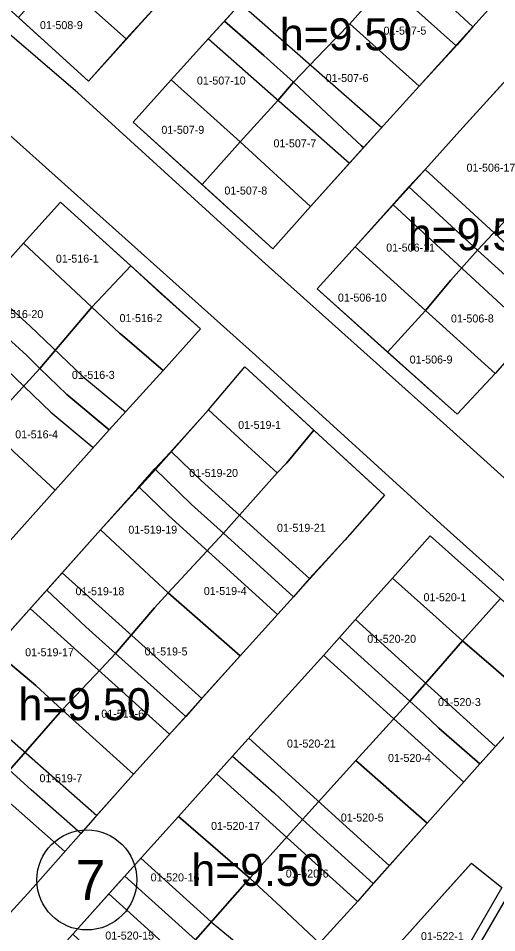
# Model space of a CAD drawing. Extents: x 413946 to 415528, y 4453939 to 4454944.
# Drawn here: x 415344.5 to 415404.3, y 4454500.5 to 4454614.8 of the extents above; entities that cross this region are included whole.
import ezdxf

# ---------------------------------------------------------------- set-up
doc = ezdxf.new("R2010")
doc.units = 0
for name, color, linetype in [('0_KADASTRO', 7, 'Continuous'), ('Level 27', 7, 'Continuous'), ('Level 28', 7, 'Continuous'), ('Level 30', 7, 'Continuous'), ('Level 58', 7, 'Continuous'), ('Level 59', 7, 'Continuous'), ('Level 62', 7, 'Continuous')]:
    doc.layers.add(name, color=color, linetype=linetype)

msp = doc.modelspace()

# ---------------------------------------------------------------- linework, layer by layer
at = {"layer": '0_KADASTRO'}
for points in [[(415392.52, 4454621.45), (415394.32, 4454623.55), (415398.92, 4454628.85), (415405.91, 4454636.32), (415407.9, 4454634.44), (415409.39, 4454633.1), (415414.54, 4454628.38), (415401.36, 4454613.72), (415394.73, 4454619.9)], [(415370.29, 4454614.44), (415372.34, 4454616.67), (415377.12, 4454622.06), (415381.68, 4454627.2), (415383.59, 4454629.35), (415387.91, 4454625.49), (415392.52, 4454621.45), (415390.64, 4454619.39), (415385.96, 4454614.09), (415382.84, 4454610.86), (415378.94, 4454606.78), (415375.2, 4454610.12)], [(415349.19, 4454620.07), (415354.05, 4454625.45), (415355.88, 4454627.42), (415364.64, 4454619.57), (415362.7, 4454617.4), (415358.02, 4454612.21), (415352.81, 4454616.85)], [(415385.96, 4454614.09), (415390.64, 4454619.39), (415392.52, 4454621.45), (415394.73, 4454619.9), (415401.36, 4454613.72), (415399.38, 4454611.47), (415394.62, 4454606.3)], [(415344.53, 4454614.87), (415349.19, 4454620.07), (415352.81, 4454616.85), (415358.02, 4454612.21), (415353.29, 4454606.93)], [(415363.64, 4454607.07), (415368.36, 4454612.28), (415370.29, 4454614.44), (415375.2, 4454610.12), (415378.94, 4454606.78), (415376.95, 4454604.5), (415372.27, 4454599.33)], [(415378.94, 4454606.78), (415382.84, 4454610.86), (415385.96, 4454614.09), (415394.62, 4454606.3), (415389.82, 4454600.98), (415387.66, 4454598.63), (415387.42, 4454598.86), (415384.43, 4454601.65)], [(415401.93, 4454585.81), (415408.86, 4454593.19), (415411.08, 4454595.65), (415415.48, 4454600.57), (415406.83, 4454608.55), (415404.81, 4454606.31), (415400.11, 4454601.13), (415395.44, 4454595.94), (415393.34, 4454593.71)], [(415358.88, 4454601.81), (415363.64, 4454607.07), (415372.27, 4454599.33), (415367.5, 4454594)], [(415372.27, 4454599.33), (415376.95, 4454604.5), (415378.94, 4454606.78), (415384.43, 4454601.65), (415387.42, 4454598.86), (415387.66, 4454598.63), (415381.06, 4454591.26)], [(415367.5, 4454594), (415372.27, 4454599.33), (415381.06, 4454591.26), (415376.36, 4454585.96)], [(415386.63, 4454586.21), (415393.26, 4454593.63), (415393.34, 4454593.71), (415401.93, 4454585.81), (415398.6, 4454582.05), (415395.42, 4454578.26)], [(415401.93, 4454585.81), (415408.86, 4454593.19), (415410.07, 4454592.09), (415417.49, 4454585.37), (415410.74, 4454577.85)], [(415345.19, 4454586.67), (415349.81, 4454591.81), (415358.59, 4454583.85), (415353.71, 4454578.68), (415352.4, 4454579.91)], [(415338.41, 4454579.14), (415345.19, 4454586.67), (415352.4, 4454579.91), (415353.71, 4454578.68), (415347.21, 4454571), (415345.81, 4454572.43), (415345.58, 4454572.64)], [(415381.87, 4454580.97), (415386.63, 4454586.21), (415395.42, 4454578.26), (415390.69, 4454573.05)], [(415395.42, 4454578.26), (415398.6, 4454582.05), (415401.93, 4454585.81), (415410.74, 4454577.85), (415404.14, 4454570.37)], [(415353.71, 4454578.68), (415358.59, 4454583.85), (415362.36, 4454580.4), (415367.29, 4454575.96), (415362.62, 4454570.74), (415357.53, 4454575.12), (415357.16, 4454575.43)], [(415331.71, 4454571.7), (415338.41, 4454579.14), (415345.58, 4454572.64), (415345.81, 4454572.43), (415347.21, 4454571), (415343.29, 4454566.72), (415340.55, 4454563.89), (415339.16, 4454564.98), (415336.73, 4454567.11)], [(415347.21, 4454571), (415353.71, 4454578.68), (415357.16, 4454575.43), (415357.53, 4454575.12), (415362.62, 4454570.74), (415355.89, 4454563.36), (415350.59, 4454567.77)], [(415390.69, 4454573.05), (415395.42, 4454578.26), (415404.14, 4454570.37), (415399.37, 4454565.32)], [(415340.55, 4454563.89), (415343.29, 4454566.72), (415347.21, 4454571), (415350.59, 4454567.77), (415355.89, 4454563.36), (415349.15, 4454555.82), (415343.97, 4454560.6)], [(415368.28, 4454565.86), (415372.83, 4454571.21), (415381.47, 4454563.29), (415378.1, 4454559.22), (415376.89, 4454557.98), (415373.23, 4454561.29)], [(415361.58, 4454558.45), (415363.47, 4454560.48), (415368.28, 4454565.86), (415373.23, 4454561.29), (415376.89, 4454557.98), (415370.19, 4454550.42), (415366.17, 4454554.02)], [(415333.75, 4454556.43), (415335.17, 4454557.74), (415340.55, 4454563.89), (415343.97, 4454560.6), (415349.15, 4454555.82), (415342.51, 4454548.4)], [(415370.19, 4454550.42), (415376.89, 4454557.98), (415378.1, 4454559.22), (415381.47, 4454563.29), (415385.25, 4454559.79), (415390.31, 4454555.19), (415385.34, 4454549.56), (415380.92, 4454544.76), (415378.94, 4454542.48)], [(415354.8, 4454550.86), (415359.45, 4454556.04), (415361.58, 4454558.45), (415366.17, 4454554.02), (415370.19, 4454550.42), (415363.25, 4454542.97), (415359.69, 4454546.31)], [(415348.08, 4454543.29), (415354.8, 4454550.86), (415359.69, 4454546.31), (415363.25, 4454542.97), (415361.56, 4454541.11), (415356.69, 4454535.4), (415352.98, 4454538.72)], [(415363.25, 4454542.97), (415370.19, 4454550.42), (415378.94, 4454542.48), (415372.27, 4454535.1)], [(415391.29, 4454544.81), (415396.02, 4454550.11), (415404.8, 4454542.24), (415400.07, 4454536.98), (415396.34, 4454540.31)], [(415384.69, 4454537.39), (415386.64, 4454539.58), (415391.29, 4454544.81), (415396.34, 4454540.31), (415400.07, 4454536.98), (415396.21, 4454532.57), (415394.99, 4454531.17), (415393.47, 4454529.44), (415392.23, 4454530.56)], [(415341.4, 4454535.86), (415341.92, 4454536.44), (415346.16, 4454541.18), (415348.08, 4454543.29), (415352.98, 4454538.72), (415356.69, 4454535.4), (415354.88, 4454533.47), (415350.02, 4454528.33), (415346.7, 4454531.38)], [(415356.69, 4454535.4), (415361.56, 4454541.11), (415363.25, 4454542.97), (415372.27, 4454535.1), (415367.54, 4454529.87), (415365.46, 4454527.51)], [(415400.07, 4454536.98), (415404.8, 4454542.24), (415413.64, 4454534.32), (415409.05, 4454529.17), (415403.93, 4454533.63)], [(415371.29, 4454522.55), (415376.51, 4454517.95), (415380.07, 4454514.64), (415386.73, 4454522), (415393.47, 4454529.44), (415392.23, 4454530.56), (415384.69, 4454537.39), (415382.7, 4454535.18), (415377.92, 4454529.87)], [(415393.47, 4454529.44), (415394.99, 4454531.17), (415396.21, 4454532.57), (415400.07, 4454536.98), (415403.93, 4454533.63), (415409.05, 4454529.17), (415402.21, 4454521.58), (415397.09, 4454526.04), (415395.21, 4454527.84)], [(415334.73, 4454528.41), (415336.75, 4454530.66), (415341.4, 4454535.86), (415346.7, 4454531.38), (415350.02, 4454528.33), (415343.44, 4454520.82), (415339.68, 4454524.05)], [(415350.02, 4454528.33), (415354.88, 4454533.47), (415356.69, 4454535.4), (415365.46, 4454527.51), (415363.68, 4454525.56), (415358.94, 4454520.32)], [(415386.73, 4454522), (415393.47, 4454529.44), (415395.21, 4454527.84), (415397.09, 4454526.04), (415402.21, 4454521.58), (415395.65, 4454514.16)], [(415343.44, 4454520.82), (415350.02, 4454528.33), (415358.94, 4454520.32), (415354.15, 4454514.93), (415352.33, 4454512.88), (415346.15, 4454518.33)], [(415364.56, 4454515.03), (415371.29, 4454522.55), (415376.51, 4454517.95), (415380.07, 4454514.64), (415378.18, 4454512.56), (415373.45, 4454507.29)], [(415380.07, 4454514.64), (415386.73, 4454522), (415395.65, 4454514.16), (415388.87, 4454506.65)], [(415341.28, 4454518.41), (415340.61, 4454517.67), (415338.82, 4454515.67), (415336.69, 4454513.32), (415334.67, 4454511.02), (415332.54, 4454508.6), (415332.05, 4454508.05), (415330.07, 4454505.8), (415333.85, 4454502.42), (415338.85, 4454497.94), (415340.8, 4454500.07), (415345.71, 4454505.4), (415352.33, 4454512.88), (415346.15, 4454518.33), (415343.44, 4454520.82), (415341.32, 4454518.46)], [(415357.83, 4454507.56), (415359.92, 4454509.88), (415364.56, 4454515.03), (415373.45, 4454507.29), (415366.69, 4454499.58)], [(415373.45, 4454507.29), (415378.18, 4454512.56), (415380.07, 4454514.64), (415388.87, 4454506.65), (415386.96, 4454504.42), (415382.17, 4454499.17), (415377.4, 4454503.69)], [(415392.33, 4454499.34), (415399.98, 4454507.85), (415401.18, 4454509.19), (415404.98, 4454506.12), (415398.11, 4454494.21), (415397.39, 4454495.06)], [(415351.32, 4454500.3), (415357.29, 4454506.95), (415357.83, 4454507.56), (415366.69, 4454499.58), (415359.95, 4454492.25), (415358.81, 4454493.29), (415356.52, 4454495.46)], [(415366.69, 4454499.58), (415373.45, 4454507.29), (415377.4, 4454503.69), (415382.17, 4454499.17), (415377.39, 4454493.8), (415375.5, 4454491.76), (415370.54, 4454496.39)]]:
    msp.add_lwpolyline(points, close=True, dxfattribs=at)
at = {"layer": 'Level 27'}
for p, q in [((415376.36, 4454585.96), (415358.88, 4454601.81)), ((415349.81, 4454591.81), (415367.29, 4454575.96)), ((415399.37, 4454565.32), (415381.87, 4454580.97)), ((415372.83, 4454571.21), (415390.31, 4454555.19))]:
    msp.add_line(p, q, dxfattribs=at)
for points in [[(415402.79, 4454662.09), (415384.8, 4454642.09), (415371.27, 4454626.96), (415362.7, 4454617.4), (415353.29, 4454606.93)], [(415358.88, 4454601.81), (415363.64, 4454607.07), (415368.36, 4454612.28), (415372.34, 4454616.67), (415381.68, 4454627.2), (415390.33, 4454636.85), (415397, 4454644.32), (415403.75, 4454651.87), (415408.42, 4454657.05)], [(415409.56, 4454622.84), (415401.36, 4454613.72), (415394.62, 4454606.3), (415389.82, 4454600.98), (415381.06, 4454591.26), (415376.36, 4454585.96)], [(415381.87, 4454580.97), (415386.63, 4454586.21), (415395.44, 4454595.94), (415400.11, 4454601.13), (415406.83, 4454608.55), (415409.43, 4454611.44)], [(415286.85, 4454521.84), (415291.59, 4454527.07), (415298.37, 4454534.61), (415305.09, 4454541.94), (415318.4, 4454556.81), (415325.06, 4454564.24), (415331.71, 4454571.7), (415338.41, 4454579.14), (415345.19, 4454586.67), (415349.81, 4454591.81)], [(415367.29, 4454575.96), (415362.62, 4454570.74), (415355.89, 4454563.36), (415349.15, 4454555.82), (415342.51, 4454548.4), (415329.15, 4454533.51), (415322.3, 4454525.96), (415315.86, 4454518.71), (415309.04, 4454511.18), (415304.47, 4454506.04)], [(415409.03, 4454575.92), (415404.14, 4454570.37), (415399.37, 4454565.32)], [(415310.02, 4454500.93), (415314.69, 4454506.15), (415321.35, 4454513.54), (415328.03, 4454520.98), (415332.79, 4454526.26), (415336.75, 4454530.66), (415346.16, 4454541.18), (415354.8, 4454550.86), (415361.66, 4454558.38), (415368.28, 4454565.86), (415372.83, 4454571.21)], [(415390.31, 4454555.19), (415385.34, 4454549.56), (415378.94, 4454542.48), (415372.27, 4454535.1), (415363.68, 4454525.56), (415358.94, 4454520.32), (415352.33, 4454512.88), (415345.71, 4454505.4), (415340.8, 4454500.07), (415336.86, 4454495.7), (415332.18, 4454490.43), (415327.52, 4454485.21)], [(415333.05, 4454480.09), (415337.73, 4454485.35), (415344.49, 4454492.72), (415351.32, 4454500.3), (415359.92, 4454509.88), (415364.56, 4454515.03), (415371.29, 4454522.55), (415377.92, 4454529.87), (415382.7, 4454535.18), (415386.64, 4454539.58), (415391.29, 4454544.81), (415396.02, 4454550.11)], [(415396.02, 4454550.11), (415404.8, 4454542.24), (415408.62, 4454538.82)], [(415408.5, 4454528.56), (415402.21, 4454521.58), (415395.65, 4454514.16), (415386.96, 4454504.42), (415382.17, 4454499.17), (415368.73, 4454484.21), (415360.01, 4454474.61), (415355.28, 4454469.41), (415350.53, 4454464.22)], [(415371.07, 4454475.69), (415374.23, 4454479.2), (415380.92, 4454486.66), (415392.34, 4454499.33), (415401.18, 4454509.19)], [(415401.18, 4454509.19), (415404.98, 4454506.12), (415398.11, 4454494.21), (415394.18, 4454488.09), (415389.06, 4454479.28), (415383.11, 4454471.06)]]:
    msp.add_lwpolyline(points, dxfattribs=at)
at = {"layer": 'Level 28'}
msp.add_line((415353.29, 4454606.93), (415335.77, 4454622.85), dxfattribs=at)
at = {"layer": 'Level 58'}
msp.add_circle((415353.09, 4454507.08), 6.25, dxfattribs=at)
at = {"layer": 'Level 59'}
for points in [[(415399.22, 4454611.36), (415381.6, 4454627.11)], [(415372.32, 4454616.65), (415389.96, 4454601.13)], [(415368.29, 4454612.2), (415385.94, 4454596.67)], [(415395.4, 4454595.89), (415412.67, 4454580)], [(415391.37, 4454591.45), (415408.68, 4454575.52)], [(415346.02, 4454576.29), (415340.42, 4454581.37)], [(415352.59, 4454570.01), (415346.02, 4454576.29)], [(415348.59, 4454565.53), (415341.86, 4454571.97)], [(415352.59, 4454570.01), (415357.92, 4454565.58)], [(415348.59, 4454565.53), (415353.89, 4454561.12)], [(415367.39, 4454557.02), (415363.64, 4454560.63)], [(415367.39, 4454557.02), (415380.95, 4454544.71)], [(415363.3, 4454552.62), (415359.63, 4454556.16)], [(415363.3, 4454552.62), (415376.93, 4454540.25)], [(415367.45, 4454529.75), (415349.99, 4454545.47)], [(415363.44, 4454525.29), (415345.99, 4454540.99)], [(415404.19, 4454523.78), (415386.68, 4454539.63)], [(415400.2, 4454519.3), (415382.68, 4454535.16)], [(415336.73, 4454530.64), (415354.32, 4454515.12)], [(415332.72, 4454526.18), (415350.34, 4454510.64)], [(415373.34, 4454524.81), (415390.91, 4454508.85)], [(415369.32, 4454520.35), (415386.92, 4454504.37)], [(415359.84, 4454509.79), (415368.64, 4454501.86)], [(415355.82, 4454505.33), (415364.73, 4454497.3)], [(415368.64, 4454501.86), (415372.52, 4454498.64)]]:
    msp.add_lwpolyline(points, dxfattribs=at)
at = {"layer": 'Level 62'}
for p, q in [((415351.95, 4454605.45), (415332.29, 4454622.3)), ((415327.93, 4454614.06), (415351.15, 4454593.29)), ((415375.02, 4454584.48), (415351.95, 4454605.45)), ((415351.15, 4454593.29), (415374.18, 4454572.69)), ((415398.04, 4454563.83), (415375.02, 4454584.48)), ((415374.18, 4454572.69), (415397.35, 4454551.6)), ((415408.79, 4454554.15), (415398.04, 4454563.83))]:
    msp.add_line(p, q, dxfattribs=at)
for points in [[(415397.35, 4454551.6), (415406.14, 4454543.73), (415408.65, 4454541.48)], [(415406.14, 4454505.87), (415384.02, 4454467.82)]]:
    msp.add_lwpolyline(points, dxfattribs=at)

# ---------------------------------------------------------------- texts
at = {"layer": '0_KADASTRO'}
for s, p in [('01-508-9', (415347.23, 4454613.43)), ('01-507-5', (415390.18, 4454612.74)), ('01-507-10', (415366.85, 4454606.5)), ('01-507-6', (415382.95, 4454606.82)), ('01-507-9', (415362.41, 4454600.34)), ('01-507-7', (415376.42, 4454598.65)), ('01-506-17', (415400.56, 4454595.61)), ('01-507-8', (415370.29, 4454592.75)), ('01-506-11', (415390.52, 4454585.62)), ('01-516-1', (415349.22, 4454584.24)), ('01-506-10', (415384.48, 4454579.37)), ('01-516-20', (415341.55, 4454577.31)), ('01-516-2', (415357.18, 4454576.81)), ('01-506-8', (415398.61, 4454576.76)), ('01-506-9', (415393.45, 4454571.63)), ('01-516-3', (415351.22, 4454569.71)), ('01-519-1', (415372.01, 4454563.46)), ('01-516-4', (415344.14, 4454562.28)), ('01-519-20', (415365.89, 4454557.45)), ('01-519-19', (415358.28, 4454550.36)), ('01-519-21', (415376.86, 4454550.6)), ('01-519-18', (415351.68, 4454542.67)), ('01-519-4', (415367.71, 4454542.7)), ('01-520-1', (415395.18, 4454541.92)), ('01-520-20', (415388.15, 4454536.72)), ('01-519-17', (415345.38, 4454535.04)), ('01-519-5', (415360.32, 4454535.14)), ('01-520-3', (415396.99, 4454528.81)), ('01-519-6', (415354.9, 4454527.36)), ('01-520-21', (415378.11, 4454523.63)), ('01-520-4', (415390.74, 4454521.83)), ('01-519-7', (415347.17, 4454519.3)), ('01-520-5', (415384.84, 4454514.38)), ('01-520-17', (415368.62, 4454513.33)), ('01-520-16', (415361.07, 4454506.9)), ('01-520-6', (415377.96, 4454507.38)), ('01-520-15', (415355.4, 4454499.63)), ('01-522-1', (415394.86, 4454499.55))]:
    msp.add_text(s, height=1, dxfattribs=at).set_placement(p)
at = {"layer": 'Level 30'}
for p in [(415377.22, 4454610.78), (415393.23, 4454585.78), (415344.55, 4454527.05), (415366.17, 4454506.33)]:
    msp.add_text('h=9.50', height=4, dxfattribs=at).set_placement(p)
at = {"layer": 'Level 58'}
msp.add_text('7', height=5, rotation=359.4141, dxfattribs=at).set_placement((415351.65, 4454504.59))

doc.saveas('drawing.dxf')
